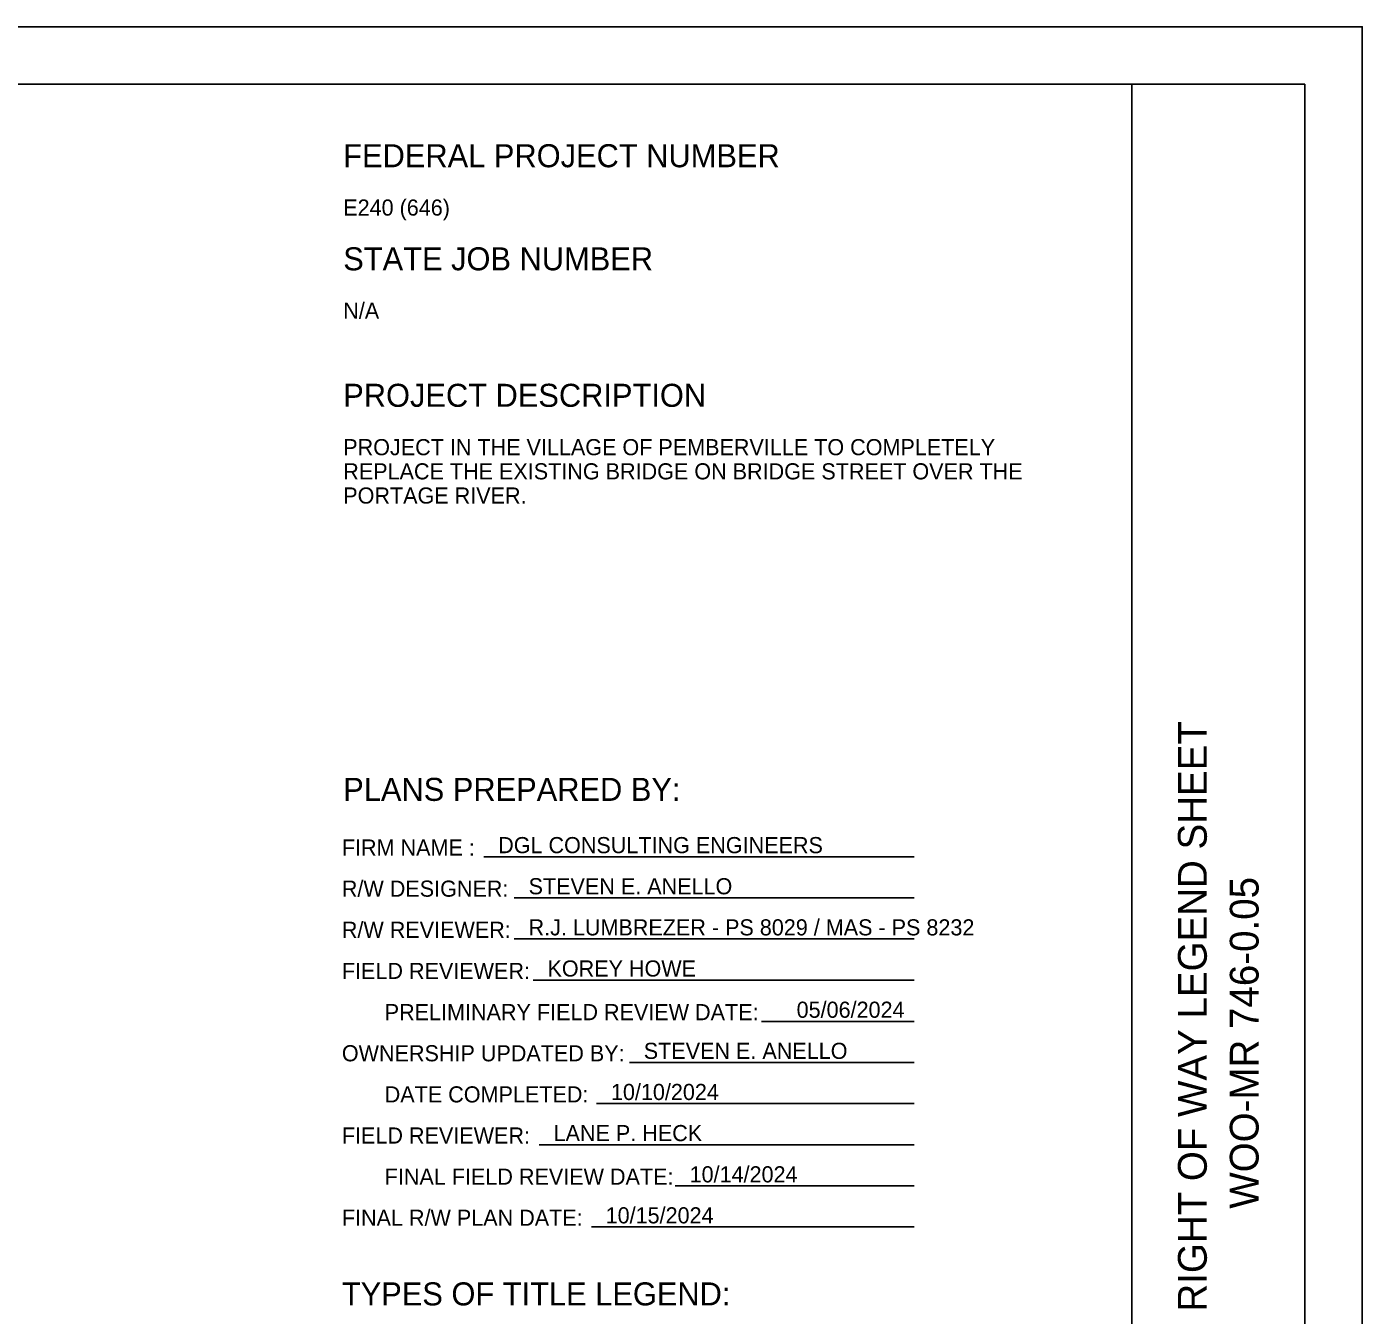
# Model space of a CAD drawing. Extents: x 0 to 34, y 0 to 22.
# Drawn here: x 22.4 to 34, y 10.81 to 22 of the extents above; entities that cross this region are included whole.
import ezdxf

# ---------------------------------------------------------------- set-up
doc = ezdxf.new("R2010")
doc.units = 0
for name, color, linetype in [('SH_Border', 7, 'Continuous'), ('SH_Cut_Line', 7, 'Continuous'), ('SH_Data', 7, 'Continuous'), ('SH_Text', 7, 'Continuous')]:
    doc.layers.add(name, color=color, linetype=linetype)

msp = doc.modelspace()

# ---------------------------------------------------------------- linework, layer by layer
at = {"layer": 'SH_Border'}
msp.add_line((32, 0.5), (32, 21.5), dxfattribs=at)
msp.add_lwpolyline([(1.5, 21.5), (33.5, 21.5), (33.5, 0.5), (1.5, 0.5)], close=True, dxfattribs=at)
at = {"layer": 'SH_Cut_Line'}
msp.add_lwpolyline([(0, 0), (34, 0), (34, 22), (0, 22)], close=True, dxfattribs=at)
at = {"layer": 'SH_Text'}
for p, q in [((26.373, 14.794), (30.11, 14.794)), ((26.637, 14.437), (30.11, 14.437)), ((26.637, 14.08), (30.11, 14.08)), ((26.801, 13.723), (30.11, 13.723)), ((28.783, 13.365), (30.11, 13.365)), ((27.637, 13.008), (30.11, 13.008)), ((27.352, 12.651), (30.11, 12.651)), ((26.855, 12.294), (30.11, 12.294)), ((28.035, 11.937), (30.11, 11.937)), ((27.307, 11.58), (30.11, 11.58))]:
    msp.add_line(p, q, dxfattribs=at)

# ---------------------------------------------------------------- texts
at = {"layer": 'SH_Data'}
msp.add_text('PROJECT DESCRIPTION', height=0.2, dxfattribs=at).set_placement((25.153, 18.7))
for s, p in [('RIGHT OF WAY LEGEND SHEET', (32.65, 10.845)), ('WOO-MR 746-0.05', (33.1, 11.739))]:
    msp.add_text(s, height=0.25, rotation=90, dxfattribs=at).set_placement(p)
at = {"layer": 'SH_Text'}
for s, height, p in [('FEDERAL PROJECT NUMBER', 0.2, (25.153, 20.78)), ('E240 (646)', 0.14, (25.153, 20.36)), ('STATE JOB NUMBER', 0.2, (25.153, 19.885)), ('N/A', 0.14, (25.153, 19.465)), ('PROJECT IN THE VILLAGE OF PEMBERVILLE TO COMPLETELY', 0.14, (25.153, 18.28)), ('REPLACE THE EXISTING BRIDGE ON BRIDGE STREET OVER THE', 0.14, (25.153, 18.07)), ('PORTAGE RIVER.', 0.14, (25.153, 17.86)), ('PLANS PREPARED BY:', 0.2, (25.153, 15.279)), ('DGL CONSULTING ENGINEERS', 0.14, (26.498, 14.825)), ('FIRM NAME :', 0.14, (25.141, 14.804)), ('STEVEN E. ANELLO', 0.14, (26.762, 14.468)), ('R/W DESIGNER:', 0.14, (25.141, 14.447)), ('R/W REVIEWER:', 0.14, (25.141, 14.09)), ('R.J. LUMBREZER - PS 8029 / MAS - PS 8232', 0.14, (26.762, 14.111)), ('FIELD REVIEWER:', 0.14, (25.141, 13.733)), ('KOREY HOWE', 0.14, (26.926, 13.754)), ('PRELIMINARY FIELD REVIEW DATE:', 0.14, (25.513, 13.375)), ('05/06/2024', 0.14, (29.089, 13.396)), ('OWNERSHIP UPDATED BY:', 0.14, (25.141, 13.018)), ('STEVEN E. ANELLO', 0.14, (27.762, 13.039)), ('DATE COMPLETED:', 0.14, (25.513, 12.661)), ('10/10/2024', 0.14, (27.477, 12.682)), ('FIELD REVIEWER:', 0.14, (25.141, 12.304)), ('LANE P. HECK', 0.14, (26.979, 12.325)), ('FINAL FIELD REVIEW DATE:', 0.14, (25.513, 11.947)), ('10/14/2024', 0.14, (28.16, 11.967)), ('FINAL R/W PLAN DATE:', 0.14, (25.141, 11.59)), ('10/15/2024', 0.14, (27.431, 11.611)), ('TYPES OF TITLE LEGEND:', 0.2, (25.141, 10.899))]:
    msp.add_text(s, height=height, dxfattribs=at).set_placement(p)

doc.saveas('drawing.dxf')
